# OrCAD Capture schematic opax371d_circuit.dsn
size A
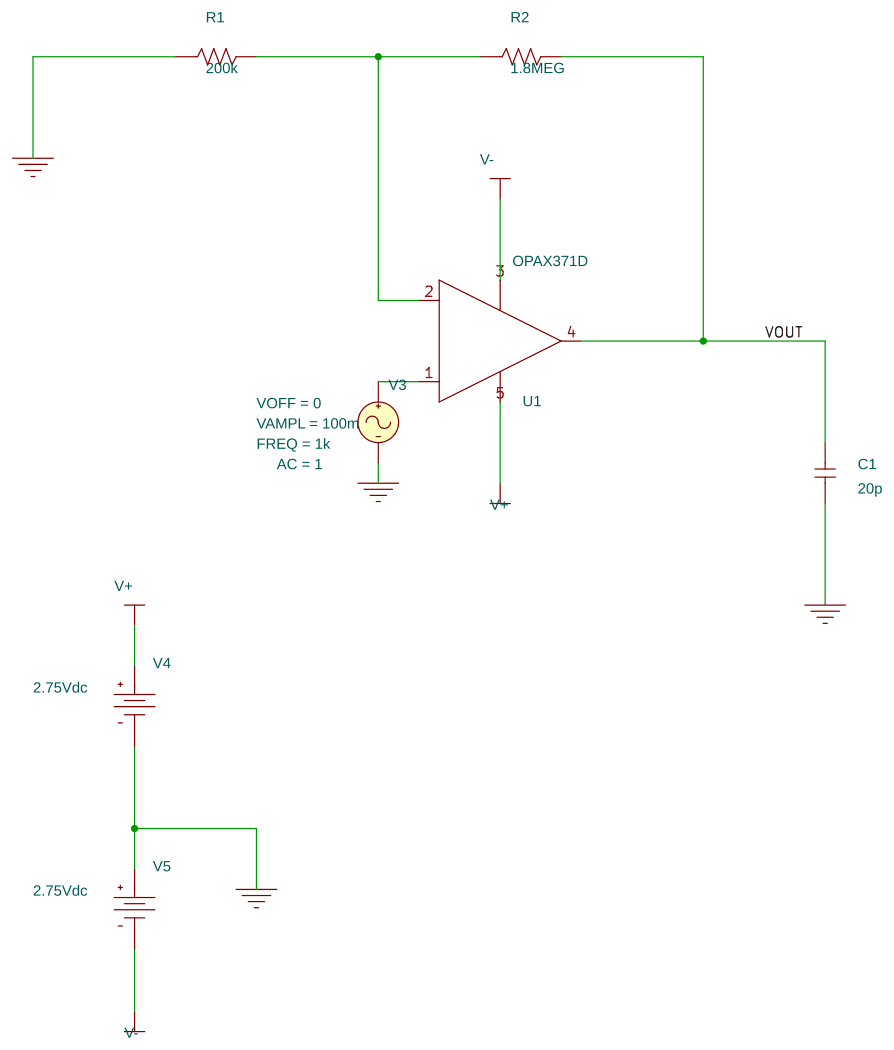
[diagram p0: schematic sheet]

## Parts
C1  20p  [cap196]
R1  200k  [AXRC05]
R2  1.8MEG  [AXRC05]
U1  OPAX371D
V3  VSIN
V4  VDC
V5  VDC

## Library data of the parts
C1 = C
R1 R2 = R
U1 = OPAX371D
V3 = VSIN: AC: 1; AppProp: Sine$Voltage$0$-1; DC: 0; FREQ: 1k; TD: 500u; VAMPL: 100m; VOFF: 0
V4 V5 = VDC: DC: 2.75Vdc

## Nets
0: C1.1 R1.1 V3.2(-) V4.1(-) V5.0(+)
V+: U1.5(V+) V4.0(+)
V-: U1.3(V-) V5.1(-)
VOUT: C1.2 R2.2 U1.4(OUT)
N03680: R1.2 R2.1 U1.2(-)
N03752: U1.1(+) V3.1(+)
